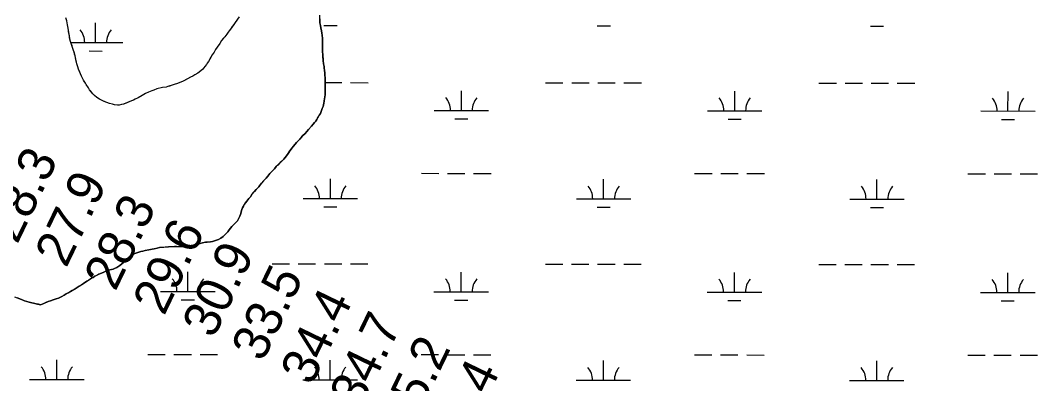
# Model space of a CAD drawing. Extents: x 3148686 to 3186545, y 916144 to 941516.
# Drawn here: x 3162319 to 3164187, y 928567 to 929233 of the extents above; entities that cross this region are included whole.
import ezdxf

# ---------------------------------------------------------------- set-up
doc = ezdxf.new("R2010")
doc.units = 0
for name, color, linetype in [('V-RIVR-RANG', 7, 'Continuous'), ('V-SITE-VEGE', 7, 'Continuous'), ('V-TOPO-SHOR', 7, 'Continuous'), ('V-WETL-SWMP', 7, 'Continuous')]:
    doc.layers.add(name, color=color, linetype=linetype)

msp = doc.modelspace()

# ---------------------------------------------------------------- linework, layer by layer
at = {"layer": 'V-SITE-VEGE'}
for points in [[(3162720.7, 929239.6), (3162713.1, 929229.4), (3162710.5, 929225.5), (3162704.6, 929217.1), (3162702.2, 929214.2), (3162700.6, 929211.4), (3162697.8, 929208), (3162694.2, 929203.1), (3162691.6, 929200.3), (3162688.4, 929196.1), (3162685, 929190.8), (3162677.3, 929179.5), (3162674.7, 929175.1), (3162670.9, 929169.7), (3162664, 929157.8), (3162662, 929155), (3162660.4, 929152.1), (3162657.6, 929148.7), (3162655.8, 929146.3), (3162653.6, 929143.9), (3162650.2, 929140.6), (3162644.6, 929136.4), (3162639.4, 929133.3), (3162635.4, 929131.1), (3162631.4, 929129.1), (3162617.8, 929121.8), (3162607.2, 929117.7), (3162601.4, 929115.3), (3162589.7, 929112), (3162586.5, 929110.8), (3162579.9, 929110.1), (3162569.5, 929107.4), (3162563.7, 929105), (3162560.3, 929104), (3162553.8, 929101.3), (3162548.8, 929099.1), (3162542.6, 929095.4), (3162535.2, 929091.4), (3162529.8, 929088.9), (3162526.4, 929087.1), (3162519.6, 929084.3), (3162508.2, 929079.8), (3162504.4, 929078.6), (3162500.4, 929077.7), (3162497, 929077.5), (3162491.7, 929078.3), (3162487.9, 929079.3), (3162482.5, 929080.8), (3162476, 929083), (3162467.8, 929086.6), (3162464.2, 929088.6), (3162459.1, 929091.9), (3162454.9, 929095.5), (3162451.9, 929098.5), (3162446, 929105.5), (3162443.6, 929109.3), (3162439.3, 929115.3), (3162438.1, 929118.1), (3162434.8, 929123.5), (3162431.2, 929130.7), (3162425.5, 929144), (3162424.1, 929148), (3162422.2, 929153.6), (3162419.3, 929168.2), (3162417.3, 929174.6), (3162416.1, 929178), (3162415.2, 929181.4), (3162410.3, 929196.5), (3162408.1, 929208.1), (3162407, 929215.1), (3162405.3, 929225), (3162403.9, 929232.4), (3162402.5, 929237.8)], [(3162560.7, 928813.6), (3162564.4, 928814.4), (3162570.2, 928815.4), (3162574.2, 928816.3), (3162591, 928818), (3162605.2, 928818.2), (3162621, 928817.9), (3162629.2, 928818.6), (3162638.2, 928820.8), (3162645.4, 928822.9), (3162649.2, 928824.1), (3162653, 928824.9), (3162659, 928826.2), (3162662, 928826.2), (3162668.2, 928826.8), (3162671.8, 928827.4), (3162676.8, 928829.1), (3162682.6, 928831.1), (3162687, 928833.7), (3162691.3, 928836.9), (3162694.5, 928840), (3162699.5, 928845.4), (3162702.3, 928849), (3162704.9, 928852), (3162707.2, 928855), (3162710.6, 928858.5), (3162717.2, 928865.5), (3162719.8, 928870.1), (3162721.7, 928874.3), (3162722.9, 928877.1), (3162725.7, 928886.3), (3162726.8, 928889.2), (3162728.6, 928892.6), (3162732.2, 928898.4), (3162734.4, 928901.4), (3162738.1, 928906.2), (3162741.1, 928909.8), (3162744.1, 928913.9), (3162751.9, 928923.1), (3162756.4, 928928.1), (3162761.4, 928934.4), (3162770.1, 928944), (3162773.1, 928947.4), (3162774.9, 928949.8), (3162776.9, 928952.3), (3162785.2, 928960.7), (3162788.8, 928964.9), (3162802.3, 928978.6), (3162809.1, 928987.2), (3162813.9, 928994.1), (3162817.8, 928999.1), (3162820, 929002.1), (3162825.6, 929009), (3162828.2, 929011.8), (3162834.5, 929018.2), (3162837.1, 929021.2), (3162841.7, 929025.6), (3162848, 929033.3), (3162853.2, 929039.3), (3162856.6, 929042.7), (3162859.2, 929045.6), (3162861.3, 929048.4), (3162862.9, 929051.2), (3162864.7, 929054), (3162869.7, 929062.6), (3162872, 929067.8), (3162873.2, 929071.4), (3162874.6, 929075), (3162876.2, 929081.3), (3162876.9, 929085.3), (3162878.3, 929096.7), (3162878.8, 929113.1), (3162878.3, 929121.9), (3162878.3, 929128.3), (3162878.1, 929132.3), (3162877.6, 929136.3), (3162877.2, 929141.9), (3162876.6, 929145.5), (3162876.6, 929148.7), (3162875.7, 929153.5), (3162874.3, 929166.7), (3162873.6, 929179.3), (3162873.5, 929200.1), (3162873, 929206.1), (3162872.6, 929209.7), (3162871.8, 929214.1), (3162870.6, 929219.6), (3162869.9, 929223.8), (3162868.9, 929228.8), (3162868.5, 929232.2), (3162869, 929242.6)], [(3162307.9, 928726.3), (3162320.9, 928721), (3162326.6, 928718.8), (3162337.2, 928715.7), (3162348, 928713.5), (3162356, 928711.2), (3162358.8, 928712.4), (3162361.6, 928713.8), (3162369.8, 928717.3), (3162374, 928718.9), (3162378.8, 928720.3), (3162384.5, 928722.3), (3162388.7, 928723.6), (3162391.5, 928725), (3162394.7, 928726.4), (3162399.1, 928729.2), (3162403.1, 928731.7), (3162406.3, 928733.1), (3162413.9, 928737.7), (3162421.2, 928742), (3162427, 928745.6), (3162434.8, 928750.8), (3162441, 928754.5), (3162449.5, 928760.1), (3162452.5, 928761.7), (3162455.5, 928763.8), (3162463.1, 928767.4), (3162470.7, 928770.9), (3162475.5, 928772.9), (3162479.7, 928774.5), (3162483.1, 928775.5), (3162488.9, 928777), (3162491.8, 928778), (3162495.8, 928779.8), (3162501.6, 928783.8), (3162505.4, 928786.7), (3162508.8, 928789.7), (3162516.5, 928797.7), (3162518.9, 928799.5), (3162524.3, 928803.2), (3162527.9, 928805), (3162530.7, 928806.2), (3162536.1, 928807.8), (3162539.7, 928809.1), (3162543.9, 928810.1), (3162547.9, 928811.3), (3162554.5, 928812.5), (3162560.7, 928813.6)]]:
    msp.add_lwpolyline(points, dxfattribs=at)
at = {"layer": 'V-TOPO-SHOR'}
for points in [[(3162523, 929085.7), (3162519.6, 929084.3), (3162512.8, 929081.6), (3162508.2, 929079.8), (3162504.4, 929078.6), (3162500.4, 929077.7), (3162497, 929077.5), (3162491.7, 929078.3), (3162487.9, 929079.3), (3162482.5, 929080.8), (3162479.1, 929082), (3162476, 929083), (3162472.4, 929084.6), (3162467.8, 929086.6), (3162464.2, 929088.6), (3162459.1, 929091.9), (3162454.9, 929095.5), (3162451.9, 929098.5), (3162448, 929103.1), (3162446, 929105.5), (3162443.6, 929109.3), (3162439.3, 929115.3), (3162438.1, 929118.1), (3162436.5, 929120.7), (3162434.8, 929123.5), (3162433, 929127.1), (3162431.2, 929130.7), (3162428.1, 929137.9), (3162425.5, 929144), (3162424.1, 929148), (3162422.2, 929153.6), (3162420.8, 929160.6), (3162420, 929164.8), (3162419.3, 929168.2), (3162418.3, 929171.4), (3162417.3, 929174.6), (3162416.1, 929178), (3162415.2, 929181.4), (3162413.6, 929186.5), (3162412.2, 929190.7), (3162410.3, 929196.5), (3162409.3, 929201.5), (3162408.7, 929204.9), (3162408.1, 929208.1), (3162407.4, 929212.1), (3162407, 929215.1), (3162406.4, 929218.9), (3162405.3, 929225), (3162403.9, 929232.4), (3162402.5, 929237.8)], [(3162717.7, 929235.6), (3162713.1, 929229.4), (3162710.5, 929225.5), (3162708, 929221.9), (3162704.6, 929217.1), (3162702.2, 929214.2), (3162700.6, 929211.4), (3162697.8, 929208), (3162696, 929205.6), (3162694.2, 929203.1), (3162691.6, 929200.3), (3162688.4, 929196.1), (3162685, 929190.8), (3162680.3, 929183.8), (3162677.3, 929179.5), (3162674.7, 929175.1), (3162670.9, 929169.7), (3162668.7, 929166), (3162666.7, 929162.6), (3162664, 929157.8), (3162662, 929155), (3162660.4, 929152.1), (3162657.6, 929148.7), (3162655.8, 929146.3), (3162653.6, 929143.9), (3162650.2, 929140.6), (3162647.6, 929138.6), (3162644.6, 929136.4), (3162639.4, 929133.3), (3162635.4, 929131.1), (3162631.4, 929129.1), (3162625.4, 929125.8), (3162621.6, 929123.8), (3162617.8, 929121.8), (3162611.4, 929119.3), (3162607.2, 929117.7), (3162601.4, 929115.3), (3162597.7, 929114.2), (3162592.7, 929112.8), (3162589.7, 929112), (3162586.5, 929110.8), (3162579.9, 929110.1), (3162569.5, 929107.4), (3162563.7, 929105), (3162560.3, 929104), (3162557.2, 929102.8), (3162553.8, 929101.3), (3162548.8, 929099.1), (3162542.6, 929095.4), (3162538.2, 929093), (3162535.2, 929091.4), (3162529.8, 929088.9), (3162526.4, 929087.1), (3162523, 929085.7)], [(3162868.7, 929236), (3162868.5, 929232.2), (3162868.9, 929228.8), (3162869.9, 929223.8), (3162870.6, 929219.6), (3162871.8, 929214.1), (3162872.6, 929209.7), (3162873, 929206.1), (3162873.5, 929200.1), (3162873.5, 929196.1), (3162873.5, 929191.5), (3162873.5, 929186.7), (3162873.6, 929179.3), (3162873.8, 929174.7), (3162874, 929170.5), (3162874.3, 929166.7), (3162874.7, 929163.5), (3162875.1, 929158.9), (3162875.7, 929153.5), (3162876.6, 929148.7), (3162876.6, 929145.5), (3162877.2, 929141.9), (3162877.6, 929136.3), (3162878.1, 929132.3), (3162878.3, 929128.3), (3162878.3, 929121.9), (3162878.6, 929117.5), (3162878.8, 929113.1), (3162878.6, 929106.1), (3162878.4, 929101.5), (3162878.3, 929096.7), (3162877.5, 929089.9), (3162876.9, 929085.3), (3162876.2, 929081.3), (3162874.6, 929075), (3162873.2, 929071.4), (3162872, 929067.8), (3162869.7, 929062.6), (3162867.7, 929059.2), (3162864.7, 929054), (3162862.9, 929051.2), (3162861.3, 929048.4), (3162859.2, 929045.6), (3162856.6, 929042.7), (3162853.2, 929039.3), (3162848, 929033.3), (3162844.7, 929029.3), (3162841.7, 929025.6), (3162837.1, 929021.2), (3162834.5, 929018.2), (3162831.7, 929015.4), (3162828.2, 929011.8), (3162825.6, 929009), (3162823.4, 929006.3), (3162820, 929002.1), (3162817.8, 928999.1), (3162813.9, 928994.1), (3162811.5, 928990.7), (3162809.1, 928987.2), (3162804.9, 928981.8), (3162802.3, 928978.6), (3162799, 928975.2), (3162796, 928972.2), (3162791.4, 928967.5), (3162788.8, 928964.9), (3162785.2, 928960.7), (3162782.9, 928958.3), (3162780.5, 928955.9), (3162776.9, 928952.3), (3162774.9, 928949.8), (3162773.1, 928947.4)], [(3162773.1, 928947.4), (3162770.1, 928944), (3162767.9, 928941.6), (3162765.4, 928938.8), (3162761.4, 928934.4), (3162759, 928931.4), (3162756.4, 928928.1), (3162751.9, 928923.1), (3162748.9, 928919.5), (3162744.1, 928913.9), (3162741.1, 928909.8), (3162738.1, 928906.2), (3162734.4, 928901.4), (3162732.2, 928898.4), (3162730.6, 928895.8), (3162728.6, 928892.6), (3162726.8, 928889.2), (3162725.7, 928886.3), (3162724.3, 928881.5), (3162722.9, 928877.1), (3162721.7, 928874.3), (3162719.8, 928870.1), (3162717.2, 928865.5), (3162714.4, 928862.5), (3162710.6, 928858.5), (3162707.2, 928855), (3162704.9, 928852), (3162702.3, 928849), (3162699.5, 928845.4), (3162694.5, 928840), (3162691.3, 928836.9), (3162687, 928833.7), (3162682.6, 928831.1), (3162676.8, 928829.1), (3162671.8, 928827.4), (3162668.2, 928826.8), (3162662, 928826.2), (3162659, 928826.2), (3162653, 928824.9), (3162649.2, 928824.1), (3162645.4, 928822.9), (3162638.2, 928820.8), (3162629.2, 928818.6), (3162621, 928817.9), (3162605.2, 928818.2), (3162601.6, 928818.2), (3162591, 928818), (3162584.4, 928817.3), (3162578.8, 928816.7), (3162574.2, 928816.3), (3162570.2, 928815.4), (3162564.4, 928814.4), (3162560.7, 928813.6), (3162554.5, 928812.5), (3162547.9, 928811.3), (3162543.9, 928810.1), (3162539.7, 928809.1), (3162536.1, 928807.8), (3162530.7, 928806.2), (3162527.9, 928805), (3162524.3, 928803.2), (3162518.9, 928799.5), (3162516.5, 928797.7), (3162511.6, 928792.5), (3162508.8, 928789.7), (3162505.4, 928786.7), (3162501.6, 928783.8), (3162495.8, 928779.8), (3162491.8, 928778), (3162488.9, 928777), (3162483.1, 928775.5), (3162479.7, 928774.5), (3162475.5, 928772.9), (3162470.7, 928770.9), (3162463.1, 928767.4), (3162458.9, 928765.4), (3162455.5, 928763.8), (3162452.5, 928761.7), (3162449.5, 928760.1), (3162444.4, 928756.7), (3162441, 928754.5), (3162434.8, 928750.8), (3162431, 928748.2), (3162427, 928745.6), (3162421.2, 928742), (3162417.5, 928739.7), (3162413.9, 928737.7), (3162409.3, 928734.9), (3162406.3, 928733.1), (3162403.1, 928731.7), (3162399.1, 928729.2), (3162394.7, 928726.4), (3162391.5, 928725), (3162388.7, 928723.6), (3162384.5, 928722.3), (3162378.8, 928720.3), (3162374, 928718.9), (3162369.8, 928717.3), (3162365.6, 928715.4), (3162361.6, 928713.8), (3162358.8, 928712.4)], [(3162358.8, 928712.4), (3162356, 928711.2), (3162352, 928712.4), (3162348, 928713.5), (3162343, 928714.5), (3162337.2, 928715.7), (3162332.4, 928717), (3162326.6, 928718.8), (3162320.9, 928721), (3162313.1, 928724.1)]]:
    msp.add_lwpolyline(points, dxfattribs=at)
at = {"layer": 'V-WETL-SWMP'}
for p, q in [((3162456.9, 929192.5), (3162457, 929228.5)), ((3162876.3, 929223.7), (3162900.3, 929223.6)), ((3163378.2, 929223.1), (3163402.2, 929223.1)), ((3163880.1, 929222.6), (3163904.1, 929222.6)), ((3162411.6, 929192.5), (3162506.9, 929192.4)), ((3162444.9, 929177.1), (3162468.9, 929177)), ((3162878.5, 929119), (3162909.3, 929119)), ((3162925.3, 929119), (3162957.3, 929118.9)), ((3163283.2, 929118.6), (3163315.2, 929118.6)), ((3163331.2, 929118.6), (3163363.2, 929118.5)), ((3163379.2, 929118.5), (3163411.2, 929118.5)), ((3163427.2, 929118.4), (3163459.2, 929118.4)), ((3163785.2, 929118.1), (3163817.2, 929118)), ((3163833.2, 929118), (3163865.2, 929118)), ((3163881.2, 929118), (3163913.2, 929117.9)), ((3163929.2, 929117.9), (3163961.2, 929117.9)), ((3163128.6, 929068), (3163128.6, 929104)), ((3163630.5, 929067.5), (3163630.5, 929103.5)), ((3164132.4, 929067), (3164132.5, 929103)), ((3163078.6, 929068.1), (3163178.6, 929068)), ((3163116.6, 929052.6), (3163140.6, 929052.6)), ((3163580.5, 929067.5), (3163680.5, 929067.4)), ((3164082.4, 929067), (3164182.4, 929066.9)), ((3163618.5, 929052.1), (3163642.5, 929052)), ((3164120.4, 929051.5), (3164144.4, 929051.5)), ((3162888, 928906.4), (3162888, 928942.4)), ((3163055.1, 928952.7), (3163087.1, 928952.6)), ((3163103.1, 928952.6), (3163135.1, 928952.6)), ((3163151.1, 928952.6), (3163183.1, 928952.5)), ((3163389.9, 928905.9), (3163389.9, 928941.9)), ((3163557, 928952.1), (3163589, 928952.1)), ((3163605, 928952.1), (3163637, 928952.1)), ((3163653, 928952), (3163685, 928952)), ((3163891.8, 928905.4), (3163891.8, 928941.4)), ((3164058.9, 928951.6), (3164090.9, 928951.6)), ((3164106.9, 928951.6), (3164138.9, 928951.5)), ((3164154.9, 928951.5), (3164186.9, 928951.5)), ((3162838, 928906.5), (3162938, 928906.4)), ((3163339.9, 928905.9), (3163439.9, 928905.8)), ((3163841.8, 928905.4), (3163941.8, 928905.3)), ((3162875.9, 928891), (3162899.9, 928891)), ((3163377.8, 928890.5), (3163401.8, 928890.4)), ((3163879.8, 928889.9), (3163903.8, 928889.9)), ((3162781, 928786.5), (3162813, 928786.4)), ((3162829, 928786.4), (3162861, 928786.4)), ((3162877, 928786.4), (3162909, 928786.3)), ((3162925, 928786.3), (3162957, 928786.3)), ((3163282.9, 928785.9), (3163314.9, 928785.9)), ((3163330.9, 928785.9), (3163362.9, 928785.8)), ((3163378.9, 928785.8), (3163410.9, 928785.8)), ((3163426.9, 928785.8), (3163458.9, 928785.7)), ((3163784.8, 928785.4), (3163816.8, 928785.4)), ((3163832.8, 928785.3), (3163864.8, 928785.3)), ((3163880.8, 928785.3), (3163912.8, 928785.3)), ((3163928.8, 928785.2), (3163960.8, 928785.2)), ((3162626.3, 928735.9), (3162626.4, 928771.9)), ((3163128.3, 928735.3), (3163128.3, 928771.3)), ((3163630.2, 928734.8), (3163630.2, 928770.8)), ((3164132.1, 928734.3), (3164132.1, 928770.3)), ((3162576.3, 928735.9), (3162676.3, 928735.8)), ((3163078.3, 928735.4), (3163178.3, 928735.3)), ((3163580.2, 928734.9), (3163680.2, 928734.8)), ((3162614.3, 928720.5), (3162638.3, 928720.4)), ((3163116.2, 928719.9), (3163140.2, 928719.9)), ((3163618.1, 928719.4), (3163642.1, 928719.4)), ((3164082.1, 928734.3), (3164182.1, 928734.2)), ((3164120, 928718.9), (3164144, 928718.8)), ((3162385.7, 928574.3), (3162385.7, 928610.3)), ((3162552.8, 928620.5), (3162584.8, 928620.5)), ((3162600.8, 928620.5), (3162632.8, 928620.4)), ((3162648.8, 928620.4), (3162680.8, 928620.4)), ((3162887.6, 928573.7), (3162887.6, 928609.7)), ((3163054.7, 928620), (3163086.7, 928620)), ((3163102.7, 928619.9), (3163134.7, 928619.9)), ((3163150.7, 928619.9), (3163182.7, 928619.9)), ((3163389.5, 928573.2), (3163389.6, 928609.2)), ((3163556.6, 928619.5), (3163588.6, 928619.4)), ((3163604.6, 928619.4), (3163636.6, 928619.4)), ((3163652.6, 928619.4), (3163684.6, 928619.3)), ((3163891.4, 928572.7), (3163891.5, 928608.7)), ((3164058.5, 928618.9), (3164090.5, 928618.9)), ((3164106.5, 928618.9), (3164138.5, 928618.9)), ((3164154.5, 928618.8), (3164186.5, 928618.8)), ((3162335.7, 928574.3), (3162435.7, 928574.2)), ((3162837.6, 928573.8), (3162937.6, 928573.7)), ((3163339.5, 928573.3), (3163439.5, 928573.2)), ((3163841.4, 928572.7), (3163941.4, 928572.6))]:
    msp.add_line(p, q, dxfattribs=at)
for points in [[(3162526.4, 929087.1), (3162523, 929085.7), (3162519.6, 929084.3), (3162512.8, 929081.6), (3162508.2, 929079.8), (3162504.4, 929078.6), (3162500.4, 929077.7), (3162497, 929077.5), (3162491.7, 929078.3), (3162487.9, 929079.3), (3162482.5, 929080.8), (3162479.1, 929082), (3162476, 929083), (3162472.4, 929084.6), (3162467.8, 929086.6), (3162464.2, 929088.6), (3162459.1, 929091.9), (3162454.9, 929095.5), (3162451.9, 929098.5), (3162448, 929103.1), (3162446, 929105.5), (3162443.6, 929109.3), (3162439.3, 929115.3), (3162438.1, 929118.1), (3162436.5, 929120.7), (3162434.8, 929123.5), (3162433, 929127.1), (3162431.2, 929130.7), (3162428.1, 929137.9), (3162425.5, 929144), (3162424.1, 929148), (3162422.2, 929153.6), (3162420.8, 929160.6), (3162420, 929164.8), (3162419.3, 929168.2), (3162418.3, 929171.4), (3162417.3, 929174.6), (3162416.1, 929178), (3162415.2, 929181.4), (3162413.6, 929186.5), (3162412.2, 929190.7), (3162410.3, 929196.5), (3162409.3, 929201.5), (3162408.7, 929204.9), (3162408.1, 929208.1), (3162407.4, 929212.1), (3162407, 929215.1), (3162406.4, 929218.9), (3162405.3, 929225), (3162403.9, 929232.4), (3162402.5, 929237.8)], [(3162717.7, 929235.6), (3162713.1, 929229.4), (3162710.5, 929225.5), (3162708, 929221.9), (3162704.6, 929217.1), (3162702.2, 929214.2), (3162700.6, 929211.4), (3162697.8, 929208), (3162696, 929205.6), (3162694.2, 929203.1), (3162691.6, 929200.3), (3162688.4, 929196.1), (3162685, 929190.8), (3162680.3, 929183.8), (3162677.3, 929179.5), (3162674.7, 929175.1), (3162670.9, 929169.7), (3162668.7, 929166), (3162666.7, 929162.6), (3162664, 929157.8), (3162662, 929155), (3162660.4, 929152.1), (3162657.6, 929148.7), (3162655.8, 929146.3), (3162653.6, 929143.9), (3162650.2, 929140.6), (3162647.6, 929138.6), (3162644.6, 929136.4), (3162639.4, 929133.3), (3162635.4, 929131.1), (3162631.4, 929129.1), (3162625.4, 929125.8), (3162621.6, 929123.8), (3162617.8, 929121.8), (3162611.4, 929119.3), (3162607.2, 929117.7), (3162601.4, 929115.3), (3162597.7, 929114.2), (3162592.7, 929112.8), (3162589.7, 929112), (3162586.5, 929110.8), (3162579.9, 929110.1), (3162569.5, 929107.4), (3162563.7, 929105), (3162560.3, 929104), (3162557.2, 929102.8), (3162553.8, 929101.3), (3162548.8, 929099.1), (3162542.6, 929095.4), (3162538.2, 929093), (3162535.2, 929091.4), (3162529.8, 929088.9), (3162526.4, 929087.1)], [(3162868.7, 929236), (3162868.5, 929232.2), (3162868.9, 929228.8), (3162869.9, 929223.8), (3162870.6, 929219.6), (3162871.8, 929214.1), (3162872.6, 929209.7), (3162873, 929206.1), (3162873.5, 929200.1), (3162873.6, 929179.3), (3162873.8, 929174.7), (3162874, 929170.5), (3162874.3, 929166.7), (3162874.7, 929163.5), (3162875.1, 929158.9), (3162875.7, 929153.5), (3162876.6, 929148.7), (3162876.6, 929145.5), (3162877.2, 929141.9), (3162877.6, 929136.3), (3162878.1, 929132.3), (3162878.3, 929128.3), (3162878.3, 929121.9), (3162878.8, 929113.1), (3162878.6, 929106.1), (3162878.4, 929101.5), (3162878.3, 929096.7), (3162877.5, 929089.9), (3162876.9, 929085.3), (3162876.2, 929081.3), (3162874.6, 929075), (3162873.2, 929071.4), (3162872, 929067.8), (3162869.7, 929062.6), (3162867.7, 929059.2), (3162864.7, 929054), (3162862.9, 929051.2), (3162861.3, 929048.4), (3162859.2, 929045.6), (3162856.6, 929042.7), (3162853.2, 929039.3), (3162848, 929033.3), (3162844.7, 929029.3), (3162841.7, 929025.6), (3162837.1, 929021.2), (3162834.5, 929018.2), (3162828.2, 929011.8), (3162825.6, 929008.9), (3162823.4, 929006.3), (3162820, 929002.1), (3162817.8, 928999.1), (3162813.9, 928994.1), (3162809.1, 928987.3)], [(3162809.1, 928987.3), (3162804.9, 928981.8), (3162802.3, 928978.6), (3162788.8, 928964.9), (3162785.2, 928960.7), (3162776.9, 928952.3), (3162774.9, 928949.8), (3162773.1, 928947.4), (3162770.1, 928944), (3162767.9, 928941.6), (3162765.4, 928938.8), (3162761.4, 928934.4), (3162759, 928931.4), (3162756.4, 928928.1), (3162751.9, 928923.1), (3162748.9, 928919.5), (3162744.1, 928913.9), (3162741.1, 928909.8), (3162738.1, 928906.2), (3162734.4, 928901.4), (3162732.2, 928898.4), (3162730.6, 928895.8), (3162728.6, 928892.6), (3162726.8, 928889.2), (3162725.7, 928886.3), (3162724.3, 928881.5), (3162722.9, 928877.1), (3162721.7, 928874.3), (3162719.8, 928870.1), (3162717.2, 928865.5), (3162714.4, 928862.5), (3162710.6, 928858.5), (3162707.2, 928855), (3162704.9, 928852), (3162702.3, 928849), (3162699.5, 928845.4), (3162694.5, 928840), (3162691.3, 928836.9), (3162687, 928833.7), (3162682.6, 928831.1), (3162676.8, 928829.1), (3162671.8, 928827.4), (3162668.2, 928826.8), (3162662, 928826.2), (3162659, 928826.2), (3162653, 928824.9), (3162649.2, 928824.1), (3162645.4, 928822.9), (3162638.2, 928820.8), (3162629.2, 928818.6), (3162621, 928817.9), (3162605.2, 928818.2), (3162601.6, 928818.2), (3162591, 928818), (3162584.4, 928817.3), (3162578.8, 928816.7), (3162574.2, 928816.3), (3162570.2, 928815.4), (3162564.4, 928814.4), (3162560.7, 928813.6), (3162554.5, 928812.5), (3162547.9, 928811.3), (3162543.9, 928810.1), (3162539.7, 928809.1), (3162536.1, 928807.8), (3162530.7, 928806.2), (3162527.9, 928805), (3162524.3, 928803.2), (3162518.9, 928799.5), (3162516.5, 928797.7), (3162511.6, 928792.5), (3162508.8, 928789.7), (3162505.4, 928786.7), (3162501.6, 928783.8), (3162495.8, 928779.8), (3162491.8, 928778), (3162488.9, 928777), (3162483.1, 928775.5), (3162479.7, 928774.5), (3162475.5, 928772.9), (3162470.7, 928770.9), (3162463.1, 928767.4), (3162458.9, 928765.4), (3162455.5, 928763.8), (3162452.5, 928761.7), (3162449.5, 928760.1), (3162444.4, 928756.7), (3162441, 928754.5), (3162434.8, 928750.8), (3162431, 928748.2), (3162427, 928745.6), (3162421.2, 928742), (3162417.5, 928739.7), (3162413.9, 928737.7), (3162409.3, 928734.9), (3162406.3, 928733.1), (3162403.1, 928731.7), (3162399.1, 928729.2), (3162394.7, 928726.4), (3162391.5, 928725), (3162388.7, 928723.6)], [(3162388.7, 928723.6), (3162384.5, 928722.3), (3162378.8, 928720.3), (3162374, 928718.9), (3162369.8, 928717.3), (3162365.6, 928715.4), (3162361.6, 928713.8), (3162358.8, 928712.4), (3162356, 928711.2), (3162348, 928713.5), (3162343, 928714.5), (3162337.2, 928715.7), (3162332.4, 928717), (3162326.6, 928718.8), (3162320.9, 928721), (3162313.1, 928724.1)]]:
    msp.add_lwpolyline(points, dxfattribs=at)
for centre, start, end in [((3162401.7, 929193), 359.1678, 40.7115), ((3162512.2, 929192.9), 139.1678, 180.7115), ((3163073.4, 929068.6), 359.1678, 40.7115), ((3163183.8, 929068.4), 139.1678, 180.7115), ((3163575.3, 929068), 359.1678, 40.7115), ((3163685.8, 929067.9), 139.1678, 180.7115), ((3164077.2, 929067.5), 359.1678, 40.7115), ((3164187.7, 929067.4), 139.1678, 180.7115), ((3162832.7, 928906.9), 359.1678, 40.7115), ((3162943.2, 928906.8), 139.1678, 180.7115), ((3163334.6, 928906.4), 359.1678, 40.7115), ((3163445.1, 928906.3), 139.1678, 180.7115), ((3163836.5, 928905.9), 359.1678, 40.7115), ((3163947, 928905.8), 139.1678, 180.7115), ((3162571.1, 928736.4), 359.1678, 40.7115), ((3162681.6, 928736.3), 139.1678, 180.7115), ((3163073, 928735.9), 359.1678, 40.7115), ((3163183.5, 928735.8), 139.1678, 180.7115), ((3163574.9, 928735.4), 359.1678, 40.7115), ((3163685.4, 928735.2), 139.1678, 180.7115), ((3164076.8, 928734.8), 359.1678, 40.7115), ((3164187.3, 928734.7), 139.1678, 180.7115), ((3162330.5, 928574.8), 359.1678, 40.7115), ((3162440.9, 928574.7), 139.1678, 180.7115), ((3162832.4, 928574.3), 359.1678, 40.7115), ((3162942.9, 928574.2), 139.1678, 180.7115), ((3163334.3, 928573.7), 359.1678, 40.7115), ((3163444.8, 928573.6), 139.1678, 180.7115), ((3163836.2, 928573.2), 359.1678, 40.7115), ((3163946.7, 928573.1), 139.1678, 180.7115)]:
    msp.add_arc(centre, 35.2, start, end, dxfattribs=at)

# ---------------------------------------------------------------- texts
at = {"layer": 'V-RIVR-RANG'}
for s, p in [('28.3', (3162312.9, 928821.1)), ('27.9', (3162402.9, 928777.6)), ('28.3', (3162493.2, 928734.6)), ('29.6', (3162582.6, 928689.7)), ('30.9', (3162673.4, 928647.8)), ('33.5', (3162763.7, 928604.8)), ('34.4', (3162853.8, 928561.5)), ('34.7', (3162944, 928518.3)), ('35.2', (3163034.1, 928475)), ('35.4', (3163124.3, 928431.8))]:
    msp.add_text(s, height=67, rotation=64.2183, dxfattribs=at).set_placement(p)

doc.saveas('drawing.dxf')
